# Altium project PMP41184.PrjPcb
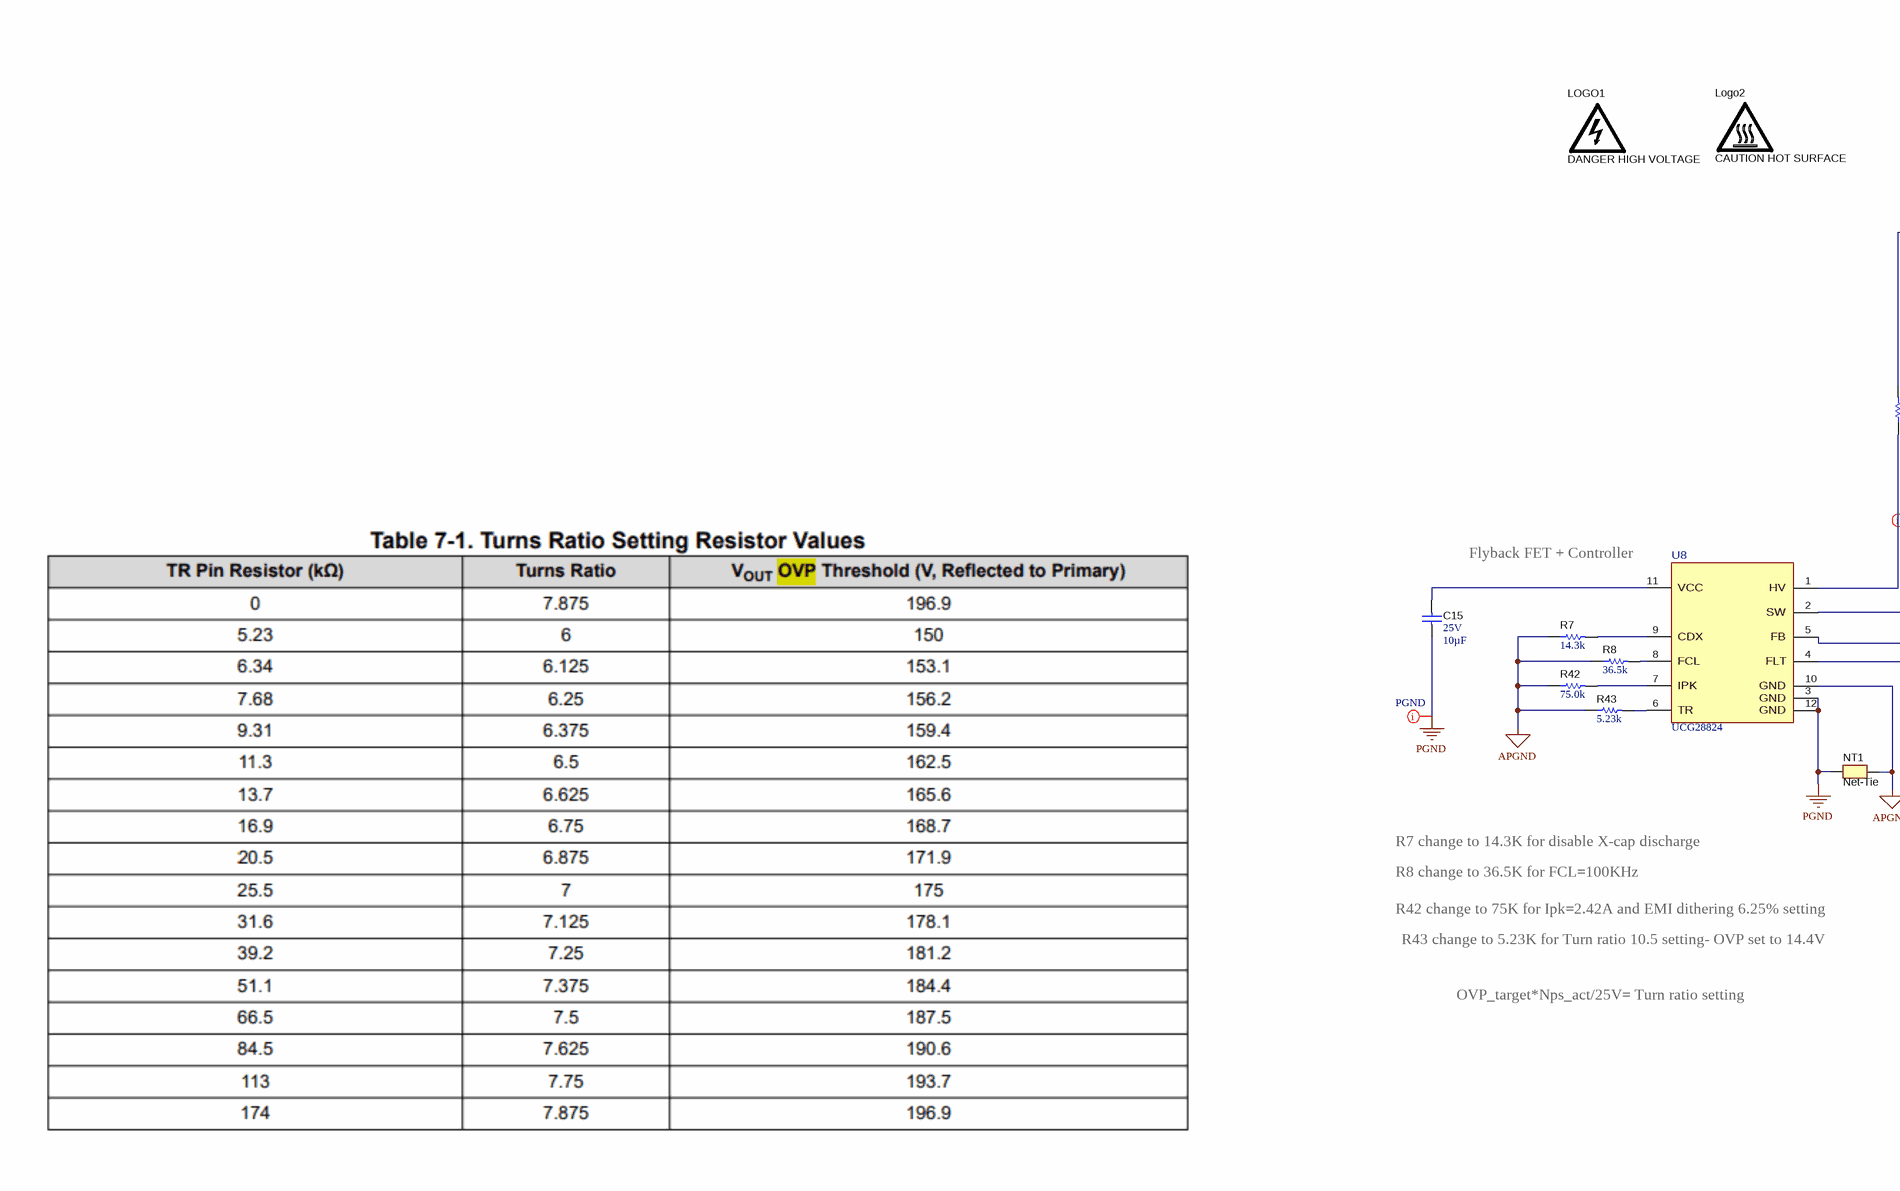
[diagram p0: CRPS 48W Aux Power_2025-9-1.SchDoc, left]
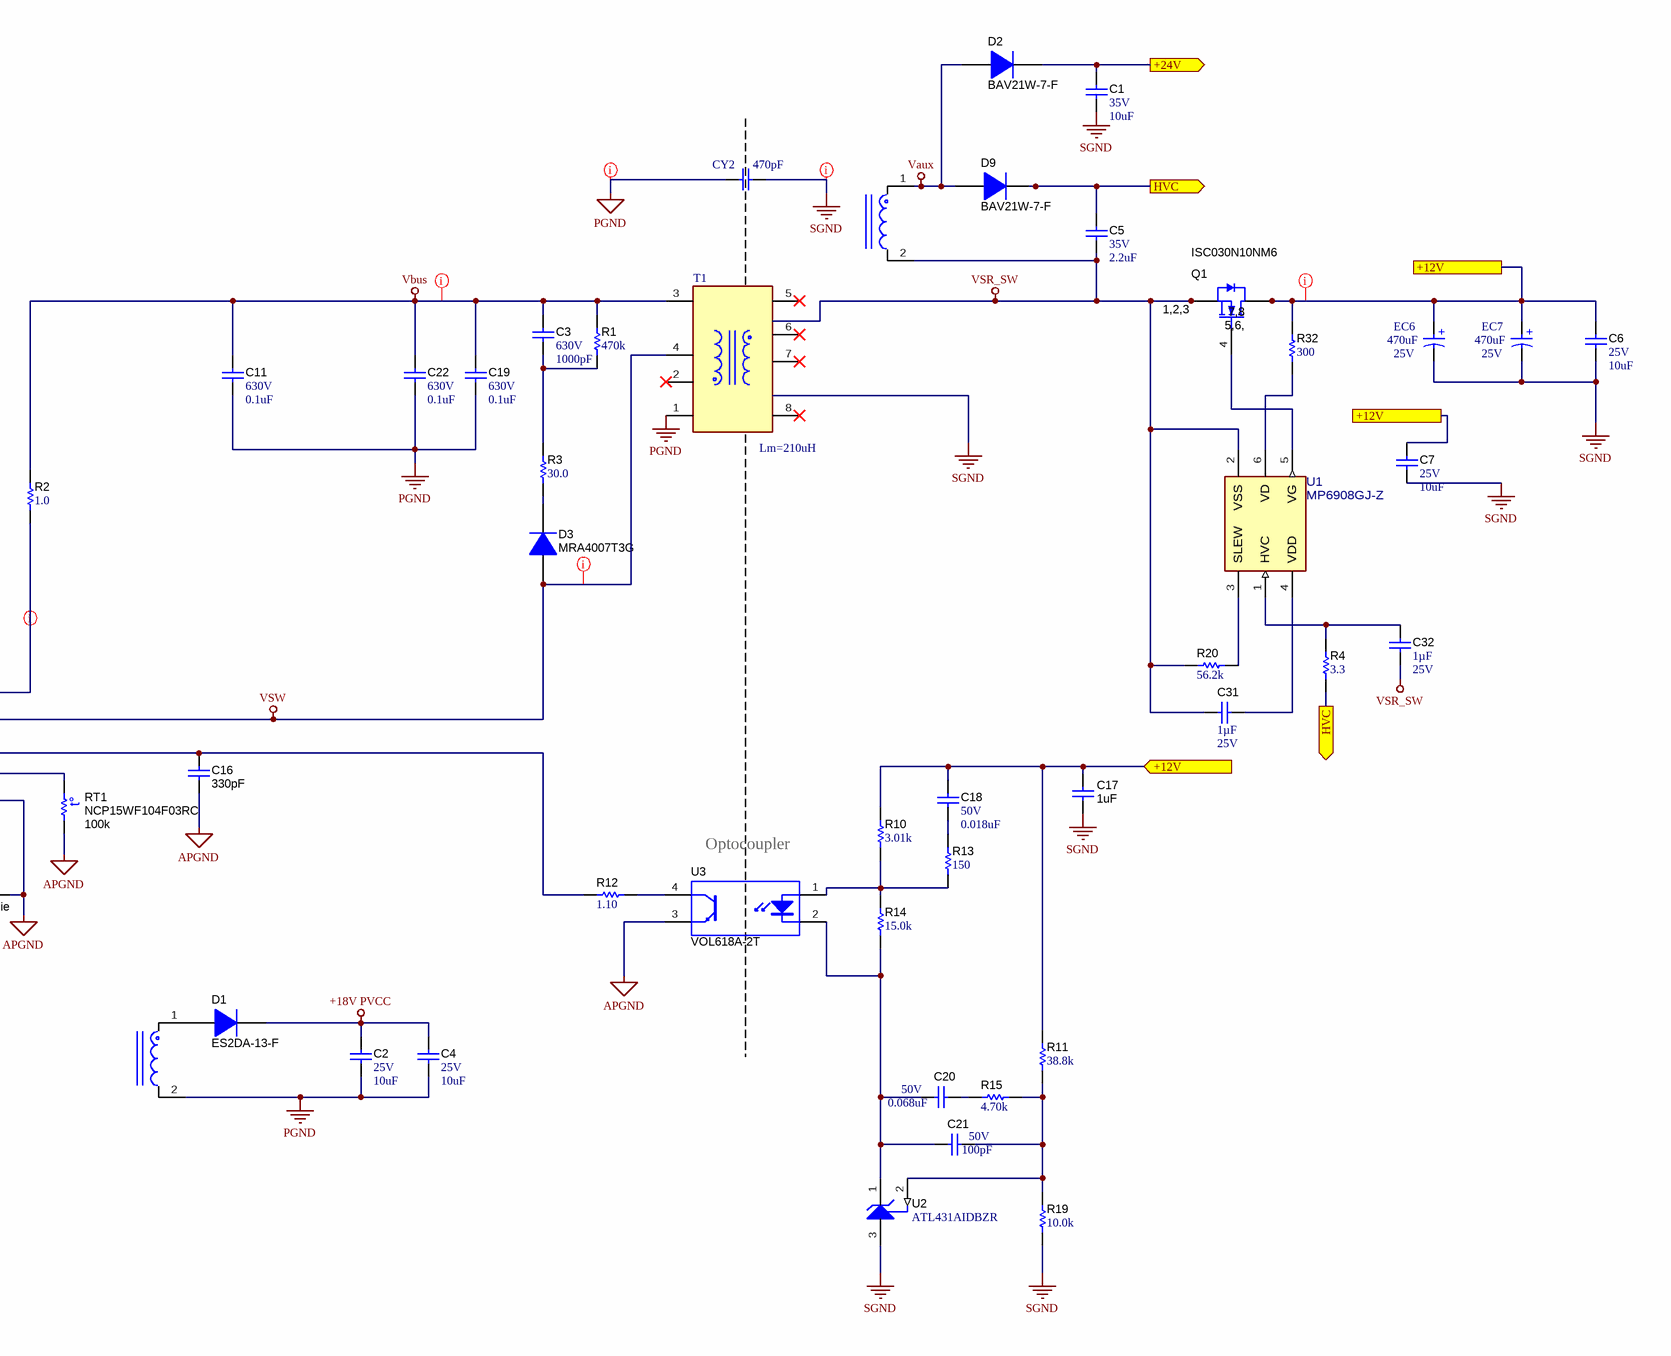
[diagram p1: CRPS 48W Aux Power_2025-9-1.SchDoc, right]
CopyrightYear: 2026; PCB_Layout: Who did the Layout?; PCB_Rev: A; PRJ_Customer: Public Release; PRJ_Engineer: Jaden Ning; PRJ_Number: PMP41184; PRJ_Title: PMP41184; SCH_Rev: A; TechSupport: http://www.ti.com/support; TID: N/A
1 sheet, 54 parts. Net scope: flat (ports and power ports of the same name join across sheets).
Board file: CRPS 48W Aux Power_2025-9-1.PcbDoc

## Sheet CRPS 48W Aux Power_2025-9-1.SchDoc
size 431 x 279 mm; Date: Not shown in title block; ApprovedBy: Not shown in title block; CheckedBy: Not shown in title block; Author: Not shown in title block; CompanyName: Not shown in title block; Engineer: Not shown in title block; Organization: Not shown in title block; Address1: Not shown in title block; Address2: Not shown in title block; Address3: Not shown in title block; Address4: Not shown in title block; DocumentNumber: 1; Revision: Use project parameter SCH_Rev; SheetNumber: 1; SheetTotal: 1; PageSetup: Record=PageOptions¦CenterHorizontal=True¦CenterVertical=True¦PrintScale=1.00¦XCorrection=1.00¦YCorrection=1.00¦PrintKind=0¦BorderSize=5000000¦LeftOffset=0¦BottomOffset=0¦Orientation=2¦PaperLength=1000¦PaperWidth=1000¦Scale=100¦PaperSource=15¦PrintQuality=600¦MediaType=1¦DitherType=10¦PaperKind=Letter¦PrintScaleMode=1

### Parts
C1  VDC_V: 35V  ValueDisplayed: 10uF  [0603]  (hidden comment: GRM188R6YA106MA73)
C2  VDC_V: 25V  ValueDisplayed: 10uF  [0805_HV]  (hidden comment: TMK212BBJ106KG-T)
C3  VDC_V: 630V  ValueDisplayed: 1000pF  [1206]  (hidden comment: GRM31BR72J102KW01L)
C4  VDC_V: 25V  ValueDisplayed: 10uF  [0805_HV]  (hidden comment: TMK212BBJ106KG-T)
C5  VDC_V: 35V  ValueDisplayed: 2.2uF  [0603]  (hidden comment: GRM188R6YA225KA12D)
C6  VDC_V: 25V  ValueDisplayed: 10uF  [0805_HV]  (hidden comment: TMK212BBJ106KG-T)
C7  VDC_V: 25V  ValueDisplayed: 10uF  [0805_HV]  (hidden comment: TMK212BBJ106KG-T)
C11  VDC_V: 630V  ValueDisplayed: 0.1uF  [1206_180]  (hidden comment: C3216X7T2W104M160AA)
C15  VDC_V: 25V  ValueDisplayed: 10µF  [0603S]  (hidden comment: GRM188R61E106KA73D)
C16  ValueDisplayed: 330pF  [0402S]  (hidden comment: GRM155R71H331KA01D)
C17  ValueDisplayed: 1uF  [0603S]  (hidden comment: C1608X7R1E105K080AB)
C18  VDC_V: 50V  ValueDisplayed: 0.018uF  [0402S]  (hidden comment: GRM155R71H183KA12D)
C19  VDC_V: 630V  ValueDisplayed: 0.1uF  [1206_180]  (hidden comment: C3216X7T2W104M160AA)
C20  VDC_V: 50V  ValueDisplayed: 0.068uF  [0402]  (hidden comment: C1005X7R1H683K050BB)
C21  VDC_V: 50V  ValueDisplayed: 100pF  [0402S]  (hidden comment: 885012205055)
C22  VDC_V: 630V  ValueDisplayed: 0.1uF  [1206_180]  (hidden comment: C3216X7T2W104M160AA)
C31  Cap_F: 1µF  VDC_V: 25V  [0603S]  (hidden comment: CGA3E1X7R1E105K080AC)
C32  Cap_F: 1µF  VDC_V: 25V  [0603S]  (hidden comment: C1608X7R1E105K080AB)
CY2  value 470pF  [CY SMD]
D1  ES2DA-13-F  [SMA]
D2  BAV21W-7-F  [SOD-123]
D3  MRA4007T3G  [SMA]
D9  BAV21W-7-F  [SOD-123]
EC6  value 470uF  Voltage: 25V  [CE05.5P254L11]  (hidden comment: ECAP_LAYDOWN)
EC7  value 470uF  Voltage: 25V  [CE05.5P254L11]  (hidden comment: ECAP_LAYDOWN)
LOGO1  DANGER HIGH VOLTAGE  [IEC_HighVoltage_Small]  (no BOM)
Logo2  CAUTION HOT SURFACE  [IEC_HotSurface_Small]  (no BOM)
NT1  Net-Tie  [Net-Tie_10milWide_30milLong]  (net tie, no BOM)
Q1  ISC030N10NM6  [PG-TDSON-8]
R1  ValueDisplayed: 470k  [0805_HV]  (hidden comment: CRCW0805470KJNEA)
R2  ValueDisplayed: 1.0  [0402S]  (hidden comment: CRCW04021R00JNED)
R3  ValueDisplayed: 30.0  [1206]  (hidden comment: RC1206FR-0730RL)
R4  ValueDisplayed: 3.3  [0402S]  (hidden comment: CRCW04023R30JNED)
R7  ValueDisplayed: 14.3k  [0402S]  (hidden comment: CRCW040214K3FKED)
R8  ValueDisplayed: 36.5k  [0402S]  (hidden comment: CRCW040236K5FKED)
R10  ValueDisplayed: 3.01k  [0402S]  (hidden comment: CRCW04023K01FKED)
R11  ValueDisplayed: 38.8k  [0603]  (hidden comment: RT0603BRD0738K8L)
R12  ValueDisplayed: 1.10  [0402S]  (hidden comment: CRCW04021R10FKED)
R13  ValueDisplayed: 150  [0402S]  (hidden comment: CRCW0402150RFKED)
R14  ValueDisplayed: 15.0k  [0402S]  (hidden comment: CRCW040215K0FKED)
R15  ValueDisplayed: 4.70k  [0402S]  (hidden comment: RC0402FR-074K7L)
R19  ValueDisplayed: 10.0k  [TNPW0603]  (hidden comment: TNPW060310K0BEEA)
R20  ValueDisplayed: 56.2k  [0603S]  (hidden comment: RC0603FR-0756K2L)
R32  ValueDisplayed: 300  [0603]  (hidden comment: RC0603FR-07300RL)
R42  ValueDisplayed: 75.0k  [0402S]  (hidden comment: CRCW040275K0FKED)
R43  ValueDisplayed: 5.23k  [0402]  (hidden comment: CRCW04025K23FKED)
RT1  NCP15WF104F03RC  value 100k  [0402S]
T1  Lm=210uH  [ATQ23.9_13.8_Remove Flywire]
T2  (no value)  [ATQ23.7_15 4+4 Pin]
T3  (no value)  [ATQ23.7_15 4+4 Pin]
U1  MP6908GJ-Z  [FP-MP6908GJ-Z_TSOT23-6-MFG]
U2  ATL431AIDBZR  [DBZ0003A_N]
U3  VOL618A-2T  [SOP254P1020X230-4]
U8  PartNumber: UCG28824  [REZ0012A-MFG]  (hidden comment: UCG28682)

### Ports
+12V, +12V (in), +24V (out), HVC (out)

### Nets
+18V PVCC: C2.1 C4.1 D1.1(K)
APGND: C16.2 NT1.2 R7.1 R8.1 R42.1 R43.1 RT1.1 U3.3(E) U8.10(GND)
PGND: C2.2 C4.2 C11.2 C15.2 C19.2 C22.2 CY2.2 NT1.1 T1.1 T3.2 U8.3(GND) U8.12(GND)
SGND: C1.2 C6.2 C7.2 C17.1 CY2.1 EC6.2(N) EC7.2(N) R19.1 U2.3(ANODE)
Vaux: D2.2(A) D9.2(A) T2.1
Vbus: C3.2 C11.1 C19.1 C22.1 R1.2 R2.2 T1.3
VSR_SW: C5.2 C31.2 C32.2 Q1.1(S) Q1.2(S) Q1.3(S) R20.1 T2.2 U1.2(VSS)
VSW: D3.2(A) T1.4 U8.2(SW)
+12V: C6.1 C7.1 C17.2 C18.1 EC6.1(P) EC7.1(P) Q1.5(D) Q1.6(D) Q1.7(D) Q1.8(D) Q1.9(D) R10.2 R11.1 R32.1 ; port +12V
+24V: C1.1 D2.1(K) ; port +24V
HVC: C5.1 D9.1(K) R4.1 ; port HVC
NetC3_1: C3.1 R1.1 R3.2
NetC15_1: C15.1 U8.11(VCC)
NetC16_1: C16.1 R12.1 U8.5(FB)
NetC18_2: C18.2 R13.2
NetC20_1: C20.1 R15.1
NetC20_2: C20.2 C21.2 R14.1 U2.1(CATHODE) U3.2(K)
NetC21_1: C21.1 R11.2 R15.2 R19.2 U2.2(REF)
NetC31_1: C31.1 U1.4(VDD)
NetC32_1: C32.1 R4.2 U1.1(HVC)
NetD1_2: D1.2(A) T3.1
NetD3_1: D3.1(K) R3.1
NetQ1_4: Q1.4(G) U1.5(VG)
NetR2_1: R2.1 U8.1(HV)
NetR7_2: R7.2 U8.9(CDX)
NetR8_2: R8.2 U8.8(FCL)
NetR10_1: R10.1 R13.1 R14.2 U3.1(A)
NetR12_2: R12.2 U3.4(C)
NetR20_2: R20.2 U1.3(SLEW)
NetR32_2: R32.2 U1.6(VD)
NetR42_2: R42.2 U8.7(IPK)
NetR43_2: R43.2 U8.6(TR)
NetRT1_2: RT1.2 U8.4(FLT)

Not connected (* = marked no-connect by the designer): T1 2* 5* 6* 7* 8*

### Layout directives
net class High Voltage: NetR2_1, Vbus
net class Switch Node: VSW
net class SGND: +12V, SGND
net class PGND: PGND

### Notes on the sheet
- (near U8) Flyback FET + Controller
- (near U3) Optocoupler
- R8 change to 36.5K for FCL=100KHz
- R7 change to 14.3K for disable X-cap discharge
- R42 change to 75K for Ipk=2.42A and EMI dithering 6.25% setting
- R43 change to 5.23K for Turn ratio 10.5 setting- OVP set to 14.4V
- OVP_target*Nps_act/25V= Turn ratio setting

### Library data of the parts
C1 = CMP-0007355-5: CAP, CERM, 10 uF, 35 V, +/- 20%, X5R, 0603; Manufacturer: Nichicon; TaMin_C: -55°C; Polarized: N; SizeAreaWB_mm2: 4.68; Value1: Unknown; U/M: EA; Value: 10uF; TaMax_C: 85°C; SizeZ_mm: 1; SizeX_mm: 1.6; SizeY_mm: 0.8; SizeArea_mm2: 1.28; Cap_F: 10µF; AEC Category: Q200
C2 C4 C6 C7 = CMP-0008414-2: CAP, CERM, 10 uF, 25 V, +/- 10%, X5R, 0805; Manufacturer: Taiyo Yuden; TaMin_C: -55°C; Polarized: N; SizeAreaWB_mm2: 6.75; Value1: Unknown; U/M: EA; Value: 10uF; TaMax_C: 85°C; SizeZ_mm: 1.45; SizeX_mm: 2; SizeY_mm: 1.25; Cap_Case: 0805; SizeArea_mm2: 2.5; Cap_F: 10µF; AEC Category: Q200
C3 = CMP-0008909-2: CAP, CERM, 1000 pF, 630 V, +/- 10%, X7R, 1206; Manufacturer: MuRata; TaMin_C: -55°C; Polarized: N; SizeAreaWB_mm2: 10.92; Value1: Unknown; U/M: EA; Value: 1000pF; TaMax_C: 125°C; SizeZ_mm: 1.35; SizeX_mm: 3.2; SizeY_mm: 1.6; SizeArea_mm2: 5.12; Cap_F: 1nF; AEC Category: Q200
C5 = CMP-0007356-4: CAP, CERM, 2.2 uF, 35 V, +/- 10%, X5R, 0603; Manufacturer: MuRata; TaMin_C: -55°C; Polarized: N; SizeAreaWB_mm2: 4.68; Value1: Unknown; U/M: EA; Value: 2.2uF; TaMax_C: 85°C; SizeZ_mm: 1; SizeX_mm: 1.6; SizeY_mm: 0.8; SizeArea_mm2: 1.28; Cap_F: 2.2µF; AEC Category: Q200
C11 C19 C22 = CMP-0008729-1: CAP, CERM, 0.1 uF, 450 V, +/- 20%, X7T, 1206; Manufacturer: TDK; TaMin_C: -55°C; Polarized: N; SizeAreaWB_mm2: 10.92; Value1: Unknown; U/M: EA; Value: 0.1uF; TaMax_C: 125°C; SizeZ_mm: 1.8; SizeX_mm: 3.2; SizeY_mm: 1.6; Cap_Case: 1206; Value2: 450V; SizeArea_mm2: 5.12; Cap_F: 100nF; AEC Category: Q200
C15 = CMP-0860569-1: CAP, CERM, 10 µF, 25 V,+/- 10%, X5R, 0603; Manufacturer: MuRata; SizeZ_mm: 1; AEC Category: Q200; AEC Qualified: N; TaMin_C: -55°C; Cap_Case: 0603; SizeY_mm: 0.8; SizeAreaWB_mm2: 4.68; SizeArea_mm2: 1.28; TaMax_C: 85°C; SizeX_mm: 1.6; Value: 10uF; U/M: EA
C16 = CMP-0006687-2: CAP, CERM, 330 pF, 50 V, +/- 10%, X7R, 0402; Manufacturer: MuRata; TaMin_C: -55°C; Polarized: N; SizeAreaWB_mm2: 3; Value1: Unknown; U/M: EA; Value: 330pF; TaMax_C: 125°C; SizeZ_mm: 0.6; SizeX_mm: 1; SizeY_mm: 0.5; Cap_Case: 0402; Value2: 50V; AEC Category: Q200
C17 = CMP-0007040-4: CAP, CERM, 1 µF, 25 V, +/- 10%, X7R, 0603; Manufacturer: TDK; Polarized: N; CompType: Capacitor; Value: 1uF; U/M: EA; Cap_F: 1µF; Value1: Unknown; VDC_V: 25V; TaMin_C: -55°C; TaMax_C: 125°C; Cap_Case: 0603; AEC Category: Q200; SizeArea_mm2: 1.28; SizeAreaWB_mm2: 4.68; SizeX_mm: 1.6; SizeY_mm: 0.8; SizeZ_mm: 1
C18 = CMP-0006681-2: CAP, CERM, 0.018 uF, 50 V, +/- 10%, X7R, 0402; Manufacturer: MuRata; TaMin_C: -55°C; Polarized: N; SizeAreaWB_mm2: 3; Value1: Unknown; U/M: EA; TaMax_C: 125°C; SizeZ_mm: 0.6; SizeX_mm: 1; SizeY_mm: 0.5; Cap_Case: 0402; Cap_F: 18nF; AEC Category: Q200
C20 = CMP-0006299-1: CAP, CERM, 0.068 uF, 50 V, +/- 10%, X7R, 0402; Manufacturer: TDK; TaMin_C: -55°C; ESR_ohm: 56.06m; Polarized: N; SizeAreaWB_mm2: 3; Value1: 0.05606 ohm; U/M: EA; TaMax_C: 125°C; SizeZ_mm: 0.6; SizeX_mm: 1; SizeY_mm: 0.5; Cap_F: 68nF; IRMS_A: 684.724mA; AEC Category: Q200
C21 = CMP-0006230-2: CAP, CERM, 100 pF, 50 V, +/- 10%, X7R, 0402; Manufacturer: Wurth Elektronik; TaMin_C: -55°C; Polarized: N; SizeAreaWB_mm2: 3; Value1: Unknown; U/M: EA; Value: 100pF; TaMax_C: 125°C; SizeZ_mm: 0.6; SizeX_mm: 1; SizeY_mm: 0.5; Cap_Case: 0402; AEC Category: Q200
C31 = CMP-0076705-1: CAP, CERM, 1 µF, 25 V,+/- 10%, X7R, AEC-Q200 Grade 1, 0603; Manufacturer: TDK; SizeAreaWB_mm2: 4.68; SizeArea_mm2: 1.28; AEC Qualified: Y; AEC Category: Q200; Value: 1uF; TaMax_C: 125°C; SizeZ_mm: 1.0; AEC Grade: 1; Polarized: N; TaMin_C: -55°C; SizeY_mm: 0.8; U/M: EA; SizeX_mm: 1.6; Cap_Case: 1.6x0.8x0.8mm
C32 = CMP-0007040-4: CAP, CERM, 1 uF, 25 V, +/- 10%, X7R, 0603; Manufacturer: TDK; TaMin_C: -55°C; Polarized: N; SizeAreaWB_mm2: 4.68; Value1: Unknown; U/M: EA; Value: 1uF; TaMax_C: 125°C; SizeZ_mm: 1; SizeX_mm: 1.6; SizeY_mm: 0.8; Cap_Case: 0603; SizeArea_mm2: 1.28; AEC Category: Q200
CY2 = 220pF Y Cap: 470pF Y1 Cap; PartNumber: TMY1471K
D1 = CMP-0076892-1: Diode, Superfast Rectifier, 200 V, 2 A, SMA; Manufacturer: Diodes Inc.; SizeAreaWB_mm2: 37.3428; Vr_V: 200V; SizeArea_mm2: 16.3228; TJmax_C: 150°C; AEC Category: Q101; Value: 200V; SizeZ_mm: 2.87; Green_REACh: Incomplete; Io_A: 2A; Vf_V: 920mV; SizeY_mm: 2.92; Value2: 0.92V; Green_Lifecycle: Not Set; U/M: EA; SizeX_mm: 5.59; RJC_CperW: 20.0
D2 D9 = CMP-0029031-2: Diode, Switching, 200 V, 0.2 A, SOD-123; Manufacturer: Diodes Inc.; Green_REACh: Passed; SizeArea_mm2: 6.545; TJmax_C: 150°C; Value2: 1.25V; Io_A: 200mA; SizeAreaWB_mm2: 13.095; SizeY_mm: 1.7; Value: 200V; Green_Lifecycle: Active; SizeX_mm: 3.85; SizeZ_mm: 1.35; AEC Category: Q101; Value1: 0.2A
D3 = CMP-0077082-2: Diode, Standard Recovery Rectifier, 1000 V, 1 A, AEC-Q101, SMA; Manufacturer: ON Semiconductor; Value2: 1.1V; TJmax_C: 175°C; SizeX_mm: 5.59; Green_Lifecycle: Active; Value1: 1A; Green_REACh: Passed; AEC Qualified: Y; AEC Category: Q101; SizeArea_mm2: 16.3228; SizeY_mm: 2.92; SizeAreaWB_mm2: 37.3428; Value: 1000V; RJC_CperW: 16.2; SizeZ_mm: 2.87; Vr_V: 1kV
EC6 EC7 = ECAP_LAYDOWN: 25V/470uF D5.5*11mm; PartNumber: NPXC1001E471MJTM; Manufacturer: Yongming
LOGO1 = CMP-0074835-1: IEC 61010-1 High Voltage Warning; SymbolCreator: a0412235
Logo2 = CMP-0074837-2: IEC 61010-1 Hot Surface Warning; Manufacturer: Texas Instruments; CompType: IC; AEC Category: Q200; SymbolCreator: a0412235
NT1 = CMP-0078142-6: Single point connection between nets.
Q1 = CMP-0001046-2: MOSFET, N-CH, 150 V, 87 A, PG-TDSON-8; PartNumber: BSC093N15NS5ATMA1; Alternate Manufacturer: None; Manufacturer: Infineon Technologies; SizeZ_mm: 1.12; ChType: N; Value2: 33 nC; VdsMax_V: 150V; SizeX_mm: 5.99; SizeY_mm: 4.9; Vgs_V: 20V; QgTyp_nC: 33; Value: 150V; SizeArea_mm2: 29.351; AEC Category: Q101; IdsMax_A: 87A; SizeAreaWB_mm2: 55.131; U/M: EA
R1 = CMP-0020554-3: RES, 470 k, 5%, 0.125 W, AEC-Q200 Grade 0, 0805; Manufacturer: Vishay-Dale; Power_W: 125mW; TempCo: 200 ppm/C; Value: 470k; EIA_Code: E24; SizeX_mm: 2; SizeY_mm: 1.25; SizeZ_mm: 1.45; Value2: 0.125W; SizeArea_mm2: 2.5; AEC Qualified: Y; VDC_V: 150V; AEC Category: Q200; AEC Grade: 0
R2 = CMP-0026866-2: RES, 1.0, 5%, 0.063 W, 0402; Manufacturer: Vishay-Dale; Power_W: 63mW; TempCo: 200 ppm/C; Value_Code: 1R00; U/M: EA; Value: 1.0; EIA_Code: E24; Res_ohm: 1; SizeY_mm: 0.5; SizeZ_mm: 0.6; Value2: 0.063W; VDC_V: 50V; AEC Category: Q200
R3 = CMP-0018196-2: RES, 30.0, 1%, 0.25 W, 1206; Manufacturer: Yageo America; Power_W: 250mW; TempCo: 100 ppm/C; Value_Code: 30R0; U/M: EA; Value: 30.0; Res_ohm: 30; SizeX_mm: 3.2; SizeY_mm: 1.6; SizeZ_mm: 1.35; Value2: 0.25W; SizeArea_mm2: 5.12; VDC_V: 200V; AEC Category: Q200
R4 = CMP-0026926-1: RES, 3.3, 5%, 0.063 W, 0402; Manufacturer: Vishay-Dale; Power_W: 63mW; TempCo: 200 ppm/C; Value_Code: 3R30; U/M: EA; Value: 3.3; EIA_Code: E24; SizeX_mm: 1; SizeY_mm: 0.5; SizeZ_mm: 0.6; Value2: 0.063W; VDC_V: 50V; AEC Category: Q200
R7 = CMP-0026016-2: RES, 14.3 k, 1%, 0.063 W, 0402; Manufacturer: Vishay-Dale; Power_W: 63mW; TempCo: 100 ppm/C; Value_Code: 14k3; U/M: EA; Value: 14.3k; EIA_Code: E96; SizeX_mm: 1; SizeY_mm: 0.5; SizeZ_mm: 0.6; Value2: 0.063W; VDC_V: 50V; AEC Category: Q200
R8 = CMP-0026315-1: RES, 36.5 k, 1%, 0.063 W, 0402; Manufacturer: Vishay-Dale; Power_W: 63mW; TempCo: 100 ppm/C; Value_Code: 36k5; U/M: EA; Value: 36.5k; EIA_Code: E96; SizeX_mm: 1; SizeY_mm: 0.5; SizeZ_mm: 0.6; Value2: 0.063W; VDC_V: 50V; AEC Category: Q200
R10 = CMP-0026329-2: RES, 3.01 k, 1%, 0.063 W, AEC-Q200 Grade 0, 0402; Manufacturer: Vishay-Dale; Power_W: 63mW; TempCo: 100 ppm/C; Value_Code: 3k01; Value: 3.01k; EIA_Code: E96; SizeX_mm: 1; SizeY_mm: 0.5; SizeZ_mm: 0.6; Value2: 0.063W; AEC Qualified: Y; VDC_V: 50V; AEC Category: Q200; AEC Grade: 0
R11 = CMP-0024175-2: RES, 38.8 k, 0.1%, 0.1 W, 0603; Manufacturer: Yageo America; Power_W: 100mW; TempCo: 25 ppm/C; Value_Code: 38k8; U/M: EA; Value: 38.8k; EIA_Code: E192; SizeX_mm: 1.6; SizeY_mm: 0.8; SizeZ_mm: 1; Value2: 0.1W; SizeArea_mm2: 1.28; VDC_V: 75V; AEC Category: Q200
R12 = CMP-0026133-1: RES, 1.10, 1%, 0.063 W, 0402; Manufacturer: Vishay-Dale; Power_W: 63mW; TempCo: 100 ppm/C; Value_Code: 1R10; U/M: EA; Value: 1.10; EIA_Code: E96; Res_ohm: 1.1; SizeX_mm: 1; SizeY_mm: 0.5; SizeZ_mm: 0.6; Value2: 0.063W; VDC_V: 50V; AEC Category: Q200
R13 = CMP-0026022-3: RES, 150, 1%, 0.063 W, AEC-Q200 Grade 0, 0402; Manufacturer: Vishay-Dale; Power_W: 63mW; TempCo: 100 ppm/C; Value_Code: 150R; Value: 150; EIA_Code: E96; SizeX_mm: 1; SizeY_mm: 0.5; SizeZ_mm: 0.6; Value2: 0.063W; AEC Qualified: Y; VDC_V: 50V; AEC Category: Q200; AEC Grade: 0
R14 = CMP-0026027-3: RES, 15.0 k, 1%, 0.063 W, AEC-Q200 Grade 0, 0402; Manufacturer: Vishay-Dale; Power_W: 63mW; TempCo: 100 ppm/C; Value_Code: 15k0; Value: 15.0k; EIA_Code: E96; Res_ohm: 15k; SizeX_mm: 1; SizeY_mm: 0.5; SizeZ_mm: 0.6; Value2: 0.063W; AEC Qualified: Y; VDC_V: 50V; AEC Category: Q200; AEC Grade: 0
R15 = CMP-0026739-1: RES, 4.70 k, 1%, 0.0625 W, 0402; Manufacturer: Yageo America; Power_W: 62.5mW; TempCo: 100 ppm/C; Value_Code: 4k70; U/M: EA; Value: 4.70k; Res_ohm: 4.7k; SizeX_mm: 1; SizeY_mm: 0.5; SizeZ_mm: 0.6; AEC Qualified: N; VDC_V: 50V; AEC Category: Q200
R19 = CMP-0025686-1: RES, 10.0 k, 0.1%, 0.1 W, AEC-Q200 Grade 1, 0603; Manufacturer: Vishay-Dale; Power_W: 100mW; TempCo: 25 ppm/C; Value_Code: 10k0; U/M: EA; Value: 10.0k; EIA_Code: E192; Res_ohm: 10k; SizeX_mm: 1.6; SizeY_mm: 0.85; SizeZ_mm: 0.55; Value2: 0.1W; SizeArea_mm2: 1.36; AEC Qualified: Y; VDC_V: 75V; AEC Grade: 1; AEC Category: Q200
R20 = CMP-0023186-5: RES, 56.2 k, 1%, 0.1 W, 0603; Manufacturer: Yageo; Power_W: 100mW; TempCo: 100 ppm/C; Value_Code: 56k2; Value: 56.2k; EIA_Code: E96; SizeX_mm: 1.6; SizeY_mm: 0.8; SizeZ_mm: 1; Value2: 0.1W; SizeArea_mm2: 1.28; AEC Qualified: N; VDC_V: 75V; AEC Category: Q200; SizeAreaWB_mm2: 4.68
R32 = CMP-0023013-5: RES, 300, 1%, 0.1 W, 0603; Manufacturer: Yageo; Power_W: 100mW; TempCo: 100 ppm/C; Value_Code: 300R; Value: 300; SizeX_mm: 1.6; SizeY_mm: 0.8; SizeZ_mm: 1; Value2: 0.1W; SizeArea_mm2: 1.28; AEC Qualified: N; VDC_V: 75V; AEC Category: Q200; SizeAreaWB_mm2: 4.68
R42 = CMP-0026543-2: RES, 75.0 k, 1%, 0.063 W, AEC-Q200 Grade 0, 0402; Manufacturer: Vishay-Dale; Power_W: 63mW; TempCo: 100 ppm/C; Value_Code: 75k0; Value: 75.0k; EIA_Code: E96; Res_ohm: 75k; SizeX_mm: 1; SizeY_mm: 0.5; SizeZ_mm: 0.6; Value2: 0.063W; AEC Qualified: Y; VDC_V: 50V; AEC Category: Q200; AEC Grade: 0
R43 = CMP-0026464-2: RES, 5.23 k, 1%, 0.063 W, AEC-Q200 Grade 0, 0402; Manufacturer: Vishay-Dale; Power_W: 63mW; TempCo: 100 ppm/C; Value_Code: 5k23; Value: 5.23k; EIA_Code: E96; SizeX_mm: 1; SizeY_mm: 0.5; SizeZ_mm: 0.6; Value2: 0.063W; AEC Qualified: Y; VDC_V: 50V; AEC Category: Q200; AEC Grade: 0
RT1 = CMP-0002353-2: Thermistor NTC, 100k ohm, 1%, 0402; Manufacturer: MuRata; TaMax_C: 125°C; SizeX_mm: 1; SizeY_mm: 0.5; TaMin_C: -40°C; Power_W: 100mW; SizeZ_mm: 0.6; SizeAreaWB_mm2: 3; U/M: EA
T1 = ATQ23_15 4_4 Pin: Lm=210uH, Turns ratio=21:2:4:3; Manufacturer: AWK; Value: EDI2721
T2 T3 = Aux winding
U1 = CMP-0086802-1: FAST TURN-OFF INTELLIGENT RECTIF; Manufacturer: Monolithic Power Systems; SizeZ_mm: 1mm
U2 = CMP-0066199-1: 2.5V Low Iq Adjustable Precision Shunt Regulator, DBZ0003A (SOT-23-3); Alternate Manufacturer: Texas Instruments; SizeAreaWB_mm2: 14.0; U/M: EA; SizeZ_mm: 1.12; SizeX_mm: 2.5; SizeY_mm: 3.0; SizeArea_mm2: 7.5; CompType: IC
U3 = CMP-0006160-3: Optocoupler, 5 kV, 63-125% CTR, SMT; Manufacturer: Vishay-Semiconductor; CTR (Max): 125%; SizeAreaWB_mm2: 74.42; CTR (Min): 63%; SizeZ_mm: 2.3; SizeX_mm: 10.2; SizeY_mm: 4.1; SizeArea_mm2: 41.82; Voltage_Isolation_Vrms: 5kV
U8 = CMP-0121635-2: Manufacturer: Texas Instruments; SizeZ_mm: 1mm; Standoff Height: 0mm; AEC Category: Q200; CompType: IC

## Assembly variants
001: not fitted CY2 FID1 FID2 FID3 T2 T3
